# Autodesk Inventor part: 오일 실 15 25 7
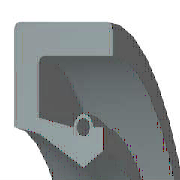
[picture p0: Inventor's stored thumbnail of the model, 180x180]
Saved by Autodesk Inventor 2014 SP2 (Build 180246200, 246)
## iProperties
Created: 2012-02
Part Number: 오일 실 15 25 7
Material: 고무
Description: 오일-실
Document SubType Name: Modeling
Standard: KS B 2804
Designer: mduedu
Standards Organization: KS
Language: ko-KR
Size Designation: S - 15 25 7
Categories: <MemberInstance><Categories><Category DisplayName="샤프트 부품" InternalName="7f7aeb1f-a693-4053-b835-cee3144e0d98" Mnemonic="SHFT"><Category DisplayName="실링" Intern
Density: 0.93 g/cm^3
Appearance: 고무 - 검은색 - 버전 1.1
IsCustomPart: 1
Author: mduedu
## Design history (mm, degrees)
revolve "본체" stored, may be unused: angle "d17" = 90 deg
revolve "스프링1" stored, may be unused: angle "d18" = 90 deg
body "Solid1"
sketch "스케치1"
  geometry: L1 (0, 12.5)-(7, 12.5); L2 (7, 12.5)-(7, 11.25); L3 (7, 11.25)-(1.75, 11.25); L4 (0, 12.5)-(0, 9.6); L5 (0, 9.6)-(1.75, 9.25); L6 (1.75, 9.25)-(4.9, 7.5); L7 (4.9, 7.5)-(0, 7.5); L8 (6.3, 8.375)-(6.3, 9.6); L9 (0, 0)-(9.586, 0) reference; L10 (4.9, 7.5)-(6.3, 8.375); L11 (0, 18)-(0, -3) reference; L12 (-1.917, 0)-(11.503, 0) reference; L13 (4.2, 9.6)-(1.75, 10.09); L14 (1.75, 10.09)-(1.75, 11.25); L15 (6.3, 9.6)-(5.6, 9.6); C1 r 0.455 at (4.9, 9.6); A1 r 0.7 centre (4.9, 9.6) between (5.6, 9.6) and (4.2, 9.6)
  constraints: 26 end point, 5 horizontal alignment, 4 perpendicular, 2 centre point, 2 collinear, 2 horizontal, 2 parallel, 2 point on circle, 2 point on line, 2 vertical alignment, 1 coincident
  dimensions: "d0" = 25 diameter of L1 L9 (= SD2); "d1" = 16.75 diameter of L8.start L9 (= ABDM); "d2" = 1.25 distance of L1.end L2.end (computed from SD); "d3" = 0.91 diameter of C1 (= SPDI); "d4" = 1.4 diameter of A1 (= SPDA); "d5" = 15 diameter of L6.end L9 (= NND); "d6" = 18.5 diameter of L5.end L9 (= TKDM); "d7" = 19.2 diameter of L4.end L9 (= HLDM); "d8" = 4.9 distance from line of C1.centre L4 (= SPDST); "d9" = 6.3 distance between parallel lines of L8 L4 (= SDI); "d10" = 7 distance between parallel lines of L2 L4 (= SWDT); "d12" = 1.75 distance between parallel lines of L14 L4 (= SD)
fillet "모깎기1" dims "d11" = 0.3 (= RR)
other parameters: "SD2" = 25 [user parameter; used in 1 equation term], "SWDT" = 7 [user parameter; used in 1 equation term], "RR" = 0.3 [user parameter; used in 1 equation term], "SD" = 1.75 [user parameter; used in 2 equation terms], "NND" = 15 [user parameter; used in 1 equation term], "SPDA" = 1.4 [user parameter; used in 1 equation term], "SPDI" = 0.91 [user parameter; used in 1 equation term], "TKDM" = 18.5 [user parameter; used in 1 equation term], "HLDM" = 19.2 [user parameter; used in 1 equation term], "ABDM" = 16.75 [user parameter; used in 1 equation term], "SDI" = 6.3 [user parameter; used in 1 equation term], "SPDST" = 4.9 [user parameter; used in 1 equation term], "d13" = 0, "d14" = 0, "d15" = 0, "LAB" = 0.35 [user parameter]
